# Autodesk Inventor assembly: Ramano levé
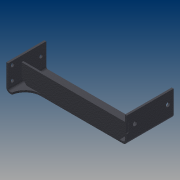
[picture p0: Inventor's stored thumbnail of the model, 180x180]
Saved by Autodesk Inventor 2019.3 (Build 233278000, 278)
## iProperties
Created: 2019-02
Part Number: Ramano levé
Material: Všeobecné
Document SubType Name: Assembly
Designer: B-hon
Author: B-hon
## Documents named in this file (3)
- C:\Users\B-hon\OneDrive\Plocha\Bakalářka22\Deska dolní\Ramano levé.iam
- C:\Users\B-hon\OneDrive\Plocha\Bakalářka22\Deska dolní\Rameno levé.ipt
- C:\Users\B-hon\OneDrive\Plocha\Bakalářka22\Deska dolní\Výztuha ramene p.ipt
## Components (2 placed, 2 different names)
1. Rameno levé:1 — Proti sobě:1, Stejný směr:1, Proti sobě:2
2. Výztuha ramene p:1 — Proti sobě:1, Stejný směr:1, Proti sobě:2
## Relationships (3: Mate 2, Flush 1)
- Proti sobě:1 [Mate]: Rameno levé:1 ↔ Výztuha ramene p:1
- Stejný směr:1 [Flush]: Rameno levé:1 ↔ Výztuha ramene p:1
- Proti sobě:2 [Mate]: Rameno levé:1 ↔ Výztuha ramene p:1
